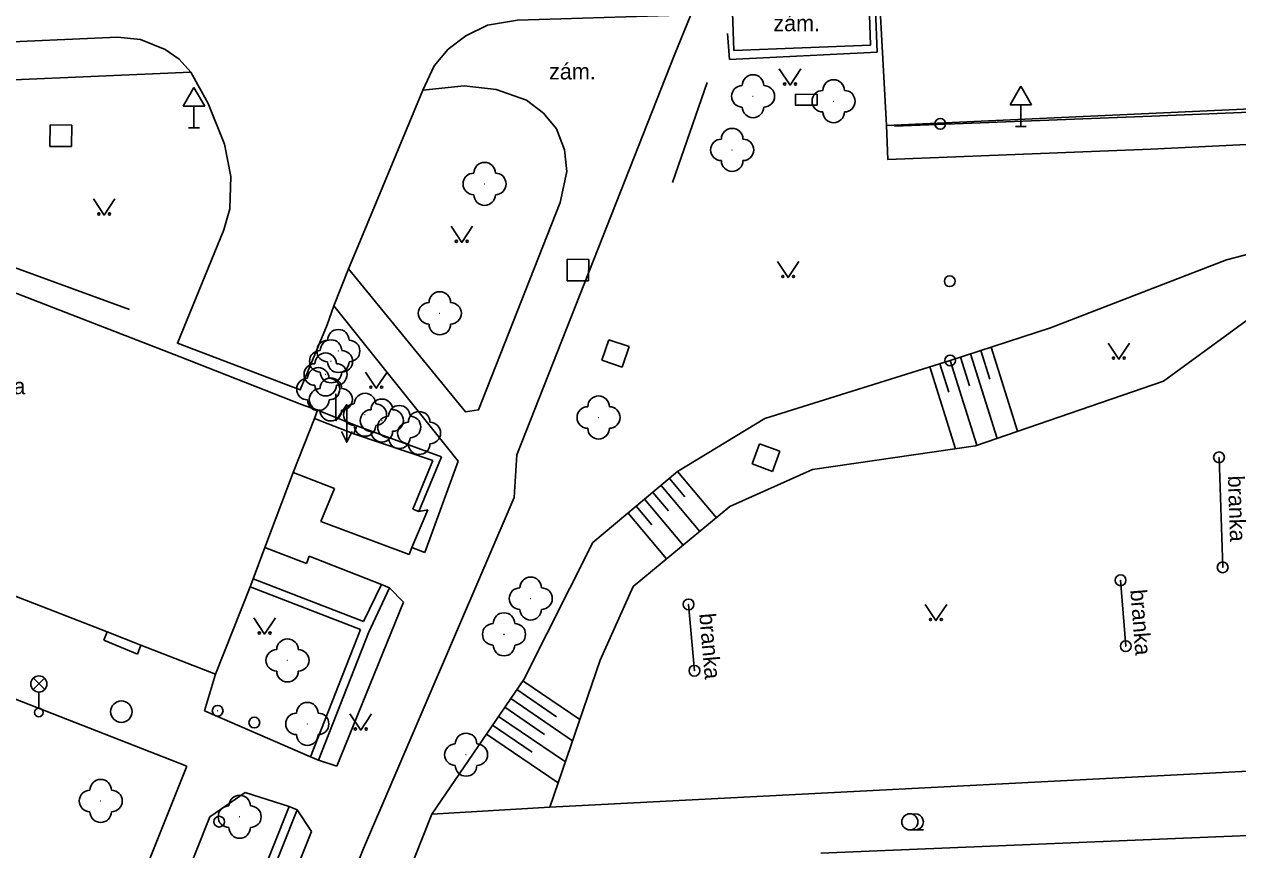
# Model space of a CAD drawing. Extents: x -737812 to -729375, y -1123000 to -1115500.
# Drawn here: x -736631 to -736574.7, y -1118354.6 to -1118316.3 of the extents above; entities that cross this region are included whole.
import ezdxf

# ---------------------------------------------------------------- set-up
doc = ezdxf.new("R2010")
doc.units = 0
for name, color, linetype in [('Doplněk polohopisu', 7, 'Continuous'), ('Doplňkové značky', 7, 'Continuous'), ('Hranice - ploty_ zdi', 7, 'Continuous'), ('Komunikace', 7, 'Continuous'), ('Pomocné popisy', 7, 'Continuous'), ('Popisy budov', 7, 'Continuous'), ('Povr_ zn_ inž_ sítí - el_', 7, 'Continuous'), ('Povr_ zn_ inž_ sítí - kan_', 7, 'Continuous'), ('Povr_ zn_ inž_ sítí - ner_', 7, 'Continuous'), ('Povr_ zn_ inž_ sítí - pl_', 7, 'Continuous'), ('Povr_ zn_ inž_ sítí - tep_', 7, 'Continuous'), ('Stavební objekty', 7, 'Continuous'), ('Výškopis', 7, 'Continuous'), ('Zeleň', 7, 'Continuous'), ('Značky druhů pozemků', 7, 'Continuous')]:
    doc.layers.add(name, color=color, linetype=linetype)

msp = doc.modelspace()

# ---------------------------------------------------------------- linework, layer by layer
at = {"layer": 'Doplněk polohopisu'}
for p, q in [((-736598.1, -1118317.51), (-736598.16, -1118315.74)), ((-736591.82, -1118315.38), (-736591.76, -1118317.25)), ((-736591.76, -1118317.25), (-736598.1, -1118317.51)), ((-736616.67, -1118329.36), (-736610.9, -1118336.57))]:
    msp.add_line(p, q, dxfattribs=at)
for points in [[(-736600.09, -1118315.84), (-736600.85, -1118317.7), (-736608.17, -1118336.28), (-736608.3, -1118338.26)], [(-736641.9, -1118319.3), (-736641.47, -1118319.3), (-736640.46, -1118319.26), (-736623.31, -1118318.51)], [(-736615.99, -1118327.65), (-736610.56, -1118334.29), (-736609.95, -1118334.2), (-736606.16, -1118324.57), (-736605.85, -1118323.13), (-736605.96, -1118322.12), (-736606.33, -1118321.14), (-736606.94, -1118320.42), (-736607.73, -1118319.81), (-736609.14, -1118319.31), (-736610.62, -1118319.14), (-736612.54, -1118319.34)], [(-736612.45, -1118340.82), (-736610.9, -1118336.57)], [(-736615.29, -1118354.56), (-736608.3, -1118338.26)], [(-736613.05, -1118340.59), (-736612.45, -1118340.82)], [(-736614.09, -1118342.46), (-736613.44, -1118343.13)], [(-736616.53, -1118350.75), (-736613.44, -1118343.13)], [(-736622.16, -1118346.47), (-736622.67, -1118348.17)], [(-736632.88, -1118347.08), (-736623.5, -1118350.75)], [(-736622.67, -1118348.17), (-736617.75, -1118350.31)], [(-736623.5, -1118350.75), (-736634.73, -1118378.78)], [(-736616.53, -1118350.75), (-736617.38, -1118350.46)], [(-736622.43, -1118353.1), (-736620.78, -1118351.97)], [(-736620.78, -1118351.97), (-736618.74, -1118352.62)], [(-736617.7, -1118353.77), (-736618.37, -1118352.77)], [(-736633.17, -1118380.05), (-736622.43, -1118353.1)], [(-736632.97, -1118392.02), (-736617.7, -1118353.77)], [(-736615.29, -1118354.56), (-736630.74, -1118393.32)]]:
    msp.add_lwpolyline(points, dxfattribs=at)
at = {"layer": 'Doplňkové značky'}
for p, q in [((-736623.16, -1118319.224), (-736623.66, -1118320.09)), ((-736623.16, -1118319.224), (-736622.66, -1118320.09)), ((-736584.78, -1118319.164), (-736585.28, -1118320.03)), ((-736584.78, -1118319.164), (-736584.28, -1118320.03)), ((-736623.66, -1118320.09), (-736622.66, -1118320.09)), ((-736623.16, -1118321.09), (-736623.16, -1118320.09)), ((-736585.28, -1118320.03), (-736584.28, -1118320.03)), ((-736584.78, -1118321.03), (-736584.78, -1118320.03)), ((-736623.41, -1118321.09), (-736622.91, -1118321.09)), ((-736585.03, -1118321.03), (-736584.53, -1118321.03))]:
    msp.add_line(p, q, dxfattribs=at)
for centre, radius in [((-736575.581, -1118336.4), 0.25), ((-736575.581, -1118336.4), 0.0005), ((-736575.41, -1118341.51), 0.25), ((-736575.41, -1118341.51), 0.0005), ((-736580.15, -1118342.11), 0.25), ((-736580.15, -1118342.11), 0.0005), ((-736600.201, -1118343.23), 0.25), ((-736600.201, -1118343.23), 0.0005), ((-736579.91, -1118345.17), 0.25), ((-736579.91, -1118345.17), 0.0005), ((-736599.931, -1118346.31), 0.25), ((-736599.931, -1118346.31), 0.0005), ((-736622.061, -1118348.17), 0.25), ((-736622.061, -1118348.17), 0.0005)]:
    msp.add_circle(centre, radius, dxfattribs=at)
at = {"layer": 'Hranice - ploty_ zdi'}
for p, q in [((-736575.58, -1118336.4), (-736575.41, -1118341.51)), ((-736580.15, -1118342.11), (-736579.91, -1118345.17)), ((-736600.2, -1118343.23), (-736599.93, -1118346.31))]:
    msp.add_line(p, q, dxfattribs=at)
for points in [[(-736598.39, -1118316.71), (-736598.3, -1118317.92), (-736591.45, -1118317.58), (-736591.52, -1118315.63)], [(-736599.34, -1118318.99), (-736600.95, -1118323.63)], [(-736535.57, -1118318.81), (-736549.9, -1118319.31), (-736564.27, -1118319.97), (-736578.72, -1118320.56), (-736590.64, -1118321.02)], [(-736626.16, -1118329.53), (-736640.74, -1118324.21)], [(-736615.6, -1118334.93), (-736611.67, -1118336.38)], [(-736612.07, -1118336.55), (-736615.74, -1118335.31)], [(-736613, -1118338.8), (-736612.07, -1118336.55)], [(-736612.72, -1118338.91), (-736611.67, -1118336.38)], [(-736618.55, -1118337.11), (-736616.64, -1118337.85)], [(-736616.64, -1118337.85), (-736617.27, -1118339.38)], [(-736613.05, -1118340.59), (-736612.31, -1118338.83)], [(-736613, -1118338.8), (-736612.72, -1118338.91)], [(-736612.72, -1118338.91), (-736612.31, -1118338.83)], [(-736617.27, -1118339.38), (-736613.17, -1118340.91)], [(-736617.93, -1118341.33), (-736619.87, -1118340.58)], [(-736613.05, -1118340.59), (-736613.17, -1118340.91)], [(-736617.93, -1118341.33), (-736617.81, -1118340.99)], [(-736614.09, -1118342.46), (-736614.46, -1118342.31), (-736617.81, -1118340.99)], [(-736615.29, -1118344.03), (-736620.42, -1118342.04)], [(-736615.29, -1118344.03), (-736614.46, -1118342.31)], [(-736615.43, -1118344.4), (-736620.56, -1118342.41)], [(-736615.06, -1118344.55), (-736614.09, -1118342.46)], [(-736615.43, -1118344.4), (-736617.75, -1118350.31)], [(-736617.38, -1118350.46), (-736615.06, -1118344.55)], [(-736544.96, -1118349.41), (-736574.22, -1118350.98), (-736606.64, -1118352.65), (-736612.12, -1118352.97)], [(-736617.75, -1118350.31), (-736617.38, -1118350.46)], [(-736642.52, -1118412.31), (-736618.74, -1118352.62)], [(-736618.37, -1118352.77), (-736642.17, -1118412.52)], [(-736612.12, -1118352.97), (-736618.92, -1118370.09), (-736634.09, -1118408.3)], [(-736618.74, -1118352.62), (-736618.37, -1118352.77)]]:
    msp.add_lwpolyline(points, dxfattribs=at)
at = {"layer": 'Komunikace'}
msp.add_line((-736615.99, -1118327.65), (-736616.67, -1118329.36), dxfattribs=at)
for points in [[(-736612.54, -1118319.34), (-736612.01, -1118318.22), (-736611.36, -1118317.44), (-736610.54, -1118316.83), (-736609.54, -1118316.33), (-736608.14, -1118316.09), (-736600.09, -1118315.84)], [(-736591.82, -1118315.38), (-736591.32, -1118315.35), (-736591.02, -1118320.98), (-736535.87, -1118318.46)], [(-736731.01, -1118328.82), (-736730.6, -1118327.33), (-736729.76, -1118325.55), (-736728.47, -1118323.96), (-736727.37, -1118322.97), (-736726.14, -1118322.1), (-736724.73, -1118321.56), (-736723.69, -1118321.36), (-736722.72, -1118321.32), (-736721.74, -1118321.25), (-736718.75, -1118321.11), (-736717.71, -1118321.12), (-736666.72, -1118318.51), (-736643.67, -1118317.64), (-736642.68, -1118317.57), (-736641.67, -1118317.52), (-736640.7, -1118317.51), (-736626.71, -1118316.89), (-736625.65, -1118316.99), (-736624.5, -1118317.46), (-736623.85, -1118317.9), (-736623.31, -1118318.51)], [(-736623.31, -1118318.51), (-736622.5, -1118319.97), (-736621.75, -1118321.86), (-736621.45, -1118323.35), (-736621.5, -1118324.86), (-736621.78, -1118325.83), (-736623.93, -1118331.1), (-736618.23, -1118333.27), (-736616.98, -1118330.25), (-736616.67, -1118329.36)], [(-736615.99, -1118327.65), (-736615.54, -1118326.57), (-736612.54, -1118319.34)]]:
    msp.add_lwpolyline(points, dxfattribs=at)
at = {"layer": 'Povr_ zn_ inž_ sítí - el_'}
for p, q in [((-736630.624, -1118347.188), (-736630.096, -1118346.66)), ((-736630.088, -1118347.185), (-736630.616, -1118346.656)), ((-736630.36, -1118347.3), (-736630.36, -1118348.05))]:
    msp.add_line(p, q, dxfattribs=at)
msp.add_lwpolyline([(-736594.24, -1118319.539), (-736595.24, -1118319.541), (-736595.24, -1118320.041), (-736594.24, -1118320.039)], close=True, dxfattribs=at)
for points in [[(-736616.57, -1118333.45), (-736616.57, -1118334.7), (-736616.07, -1118333.95), (-736616.07, -1118335.7)], [(-736616.32, -1118335.2), (-736616.07, -1118335.7), (-736615.82, -1118335.2)]]:
    msp.add_lwpolyline(points, dxfattribs=at)
for centre, radius in [((-736630.36, -1118346.925), 0.375), ((-736630.36, -1118348.25), 0.2), ((-736620.36, -1118348.72), 0.25), ((-736621.99, -1118353.32), 0.25)]:
    msp.add_circle(centre, radius, dxfattribs=at)
at = {"layer": 'Povr_ zn_ inž_ sítí - kan_'}
msp.add_circle((-736626.53, -1118348.21), 0.5, dxfattribs=at)
at = {"layer": 'Povr_ zn_ inž_ sítí - ner_'}
for p, q in [((-736596.906, -1118335.768), (-736597.252, -1118336.706)), ((-736595.968, -1118336.114), (-736596.906, -1118335.768)), ((-736596.314, -1118337.052), (-736595.968, -1118336.114)), ((-736597.252, -1118336.706), (-736596.314, -1118337.052))]:
    msp.add_line(p, q, dxfattribs=at)
at = {"layer": 'Povr_ zn_ inž_ sítí - pl_'}
for centre in [(-736588.52, -1118320.91), (-736588.08, -1118328.22), (-736588.06, -1118331.9)]:
    msp.add_circle(centre, 0.25, dxfattribs=at)
at = {"layer": 'Povr_ zn_ inž_ sítí - tep_'}
for p, q in [((-736629.835, -1118320.955), (-736629.845, -1118321.955)), ((-736628.835, -1118320.965), (-736629.835, -1118320.955)), ((-736628.845, -1118321.965), (-736628.835, -1118320.965)), ((-736629.845, -1118321.955), (-736628.845, -1118321.965)), ((-736605.835, -1118327.195), (-736605.845, -1118328.195)), ((-736604.835, -1118327.205), (-736605.835, -1118327.195)), ((-736604.845, -1118328.205), (-736604.835, -1118327.205)), ((-736605.845, -1118328.195), (-736604.845, -1118328.205)), ((-736603.911, -1118330.935), (-736604.235, -1118331.881)), ((-736602.965, -1118331.259), (-736603.911, -1118330.935)), ((-736603.289, -1118332.205), (-736602.965, -1118331.259)), ((-736604.235, -1118331.881), (-736603.289, -1118332.205))]:
    msp.add_line(p, q, dxfattribs=at)
at = {"layer": 'Stavební objekty'}
for points in [[(-736617.43, -1118334.21), (-736618.17, -1118333.94), (-736623.8, -1118331.73), (-736640.97, -1118325.07), (-736641.4, -1118324.9)], [(-736617.43, -1118334.21), (-736617.57, -1118334.59)], [(-736615.6, -1118334.93), (-736617.43, -1118334.21)], [(-736618.55, -1118337.11), (-736617.57, -1118334.59)], [(-736617.57, -1118334.59), (-736615.74, -1118335.31)], [(-736615.74, -1118335.31), (-736615.6, -1118334.93)], [(-736619.87, -1118340.58), (-736618.55, -1118337.11)], [(-736620.56, -1118342.41), (-736620.42, -1118342.04), (-736619.87, -1118340.58)], [(-736632.87, -1118342.3), (-736631.22, -1118342.94), (-736627.19, -1118344.51), (-736625.63, -1118345.12), (-736622.16, -1118346.47)], [(-736622.16, -1118346.47), (-736620.56, -1118342.41)], [(-736627.34, -1118344.89), (-736627.19, -1118344.51)], [(-736627.34, -1118344.89), (-736625.79, -1118345.54)], [(-736625.79, -1118345.54), (-736625.63, -1118345.12)]]:
    msp.add_lwpolyline(points, dxfattribs=at)
at = {"layer": 'Výškopis'}
for p, q in [((-736585.88, -1118335.52), (-736587.11, -1118331.59)), ((-736586.22, -1118332.77), (-736586.63, -1118331.44)), ((-736584.93, -1118335.19), (-736586.16, -1118331.28)), ((-736588.12, -1118333.38), (-736588.54, -1118332.05)), ((-736586.82, -1118335.84), (-736588.06, -1118331.9)), ((-736587.17, -1118333.08), (-736587.58, -1118331.75)), ((-736587.82, -1118336), (-736589.01, -1118332.2)), ((-736598.91, -1118339.21), (-736600.71, -1118337.06)), ((-736599.68, -1118339.85), (-736601.48, -1118337.7)), ((-736600.37, -1118338.24), (-736601.09, -1118337.38)), ((-736600.45, -1118340.48), (-736602.24, -1118338.35)), ((-736601.14, -1118338.88), (-736601.86, -1118338.03)), ((-736601.91, -1118339.53), (-736602.63, -1118338.67)), ((-736601.22, -1118341.12), (-736603.01, -1118338.99))]:
    msp.add_line(p, q, dxfattribs=at)
for points in [[(-736607.85, -1118346.72), (-736604.64, -1118340.36), (-736600.71, -1118337.06), (-736596.67, -1118334.6), (-736588.06, -1118331.9), (-736583.4, -1118330.39), (-736575.24, -1118327.22), (-736563.92, -1118324.29), (-736552.28, -1118322.49), (-736546.76, -1118323.72), (-736552.86, -1118324.88), (-736559.84, -1118325.66), (-736572.03, -1118328.38), (-736578.15, -1118332.86), (-736586.88, -1118335.86), (-736594.45, -1118336.97), (-736598.28, -1118338.69), (-736602.77, -1118342.4), (-736604.31, -1118345.82)], [(-736606.64, -1118352.65), (-736604.31, -1118345.82)], [(-736607.85, -1118346.72), (-736612.12, -1118352.97)], [(-736607.89, -1118346.78), (-736605.25, -1118348.58)], [(-736608.17, -1118347.19), (-736606.33, -1118348.45)], [(-736608.45, -1118347.6), (-736605.59, -1118349.56)], [(-736609.02, -1118348.43), (-736605.92, -1118350.54)], [(-736608.73, -1118348.01), (-736606.89, -1118349.27)], [(-736609.3, -1118348.84), (-736607.46, -1118350.1)], [(-736609.58, -1118349.25), (-736606.26, -1118351.52)]]:
    msp.add_lwpolyline(points, dxfattribs=at)
at = {"layer": 'Zeleň'}
for points in [[(-736535.54, -1118320.09), (-736549.85, -1118320.78), (-736564.14, -1118321.37), (-736578.74, -1118322.08), (-736590.95, -1118322.57), (-736591.02, -1118320.98)], [(-736571.98, -1118353.87), (-736594.07, -1118354.79)]]:
    msp.add_lwpolyline(points, dxfattribs=at)
for centre in [(-736597.21, -1118319.63), (-736593.47, -1118319.86), (-736598.18, -1118322.12), (-736609.67, -1118323.7), (-736611.75, -1118329.71), (-736616.46, -1118331.46), (-736616.8, -1118331.94), (-736617.05, -1118332.55), (-736617.39, -1118333.23), (-736616.81, -1118333.71), (-736615.22, -1118334.42), (-736614.44, -1118334.69), (-736613.63, -1118334.99), (-736604.38, -1118334.55), (-736612.71, -1118335.27), (-736607.53, -1118342.96), (-736608.77, -1118344.62), (-736618.82, -1118345.83), (-736617.9, -1118348.78), (-736610.53, -1118350.21), (-736627.49, -1118352.36), (-736621.04, -1118353.09)]:
    msp.add_circle(centre, 0.0005, dxfattribs=at)
for centre, start, end in [((-736597.21, -1118319.13), 360, 180), ((-736597.71, -1118319.63), 90, 270), ((-736596.71, -1118319.63), 270, 90), ((-736593.47, -1118319.36), 360, 180), ((-736593.97, -1118319.86), 90, 270), ((-736592.97, -1118319.86), 270, 90), ((-736597.21, -1118320.13), 180, 360), ((-736593.47, -1118320.36), 180, 360), ((-736598.18, -1118321.62), 360, 180), ((-736598.68, -1118322.12), 90, 270), ((-736597.68, -1118322.12), 270, 90), ((-736598.18, -1118322.62), 180, 360), ((-736609.67, -1118323.2), 360, 180), ((-736610.17, -1118323.7), 90, 270), ((-736609.17, -1118323.7), 270, 90), ((-736609.67, -1118324.2), 180, 360), ((-736611.75, -1118329.21), 360, 180), ((-736612.25, -1118329.71), 90, 270), ((-736611.25, -1118329.71), 270, 90), ((-736616.46, -1118330.96), 360, 180), ((-736611.75, -1118330.21), 180, 360), ((-736616.96, -1118331.46), 90, 270), ((-736616.8, -1118331.44), 360, 180), ((-736615.96, -1118331.46), 270, 90), ((-736617.3, -1118331.94), 90, 270), ((-736617.05, -1118332.05), 360, 180), ((-736616.3, -1118331.94), 270, 90), ((-736617.55, -1118332.55), 90, 270), ((-736616.46, -1118331.96), 180, 360), ((-736616.55, -1118332.55), 270, 90), ((-736617.89, -1118333.23), 90, 270), ((-736617.39, -1118332.73), 360, 180), ((-736616.81, -1118333.21), 360, 180), ((-736616.8, -1118332.44), 180, 360), ((-736616.89, -1118333.23), 270, 90), ((-736617.31, -1118333.71), 90, 270), ((-736617.05, -1118333.05), 180, 360), ((-736616.31, -1118333.71), 270, 90), ((-736617.39, -1118333.73), 180, 360), ((-736615.22, -1118333.92), 360, 180), ((-736614.44, -1118334.19), 360, 180), ((-736604.38, -1118334.05), 360, 180), ((-736616.81, -1118334.21), 180, 360), ((-736615.72, -1118334.42), 90, 270), ((-736614.94, -1118334.69), 90, 270), ((-736614.72, -1118334.42), 270, 90), ((-736613.63, -1118334.49), 360, 180), ((-736613.94, -1118334.69), 270, 90), ((-736612.71, -1118334.77), 360, 180), ((-736604.88, -1118334.55), 90, 270), ((-736603.88, -1118334.55), 270, 90), ((-736615.22, -1118334.92), 180, 360), ((-736614.13, -1118334.99), 90, 270), ((-736613.21, -1118335.27), 90, 270), ((-736613.13, -1118334.99), 270, 90), ((-736612.21, -1118335.27), 270, 90), ((-736614.44, -1118335.19), 180, 360), ((-736613.63, -1118335.49), 180, 360), ((-736604.38, -1118335.05), 180, 360), ((-736612.71, -1118335.77), 180, 360), ((-736607.53, -1118342.46), 360, 180), ((-736608.03, -1118342.96), 90, 270), ((-736607.03, -1118342.96), 270, 90), ((-736607.53, -1118343.46), 180, 360), ((-736608.77, -1118344.12), 360, 180), ((-736609.27, -1118344.62), 90, 270), ((-736608.27, -1118344.62), 270, 90), ((-736618.82, -1118345.33), 360, 180), ((-736608.77, -1118345.12), 180, 360), ((-736619.32, -1118345.83), 90, 270), ((-736618.32, -1118345.83), 270, 90), ((-736618.82, -1118346.33), 180, 360), ((-736617.9, -1118348.28), 360, 180), ((-736618.4, -1118348.78), 90, 270), ((-736617.4, -1118348.78), 270, 90), ((-736617.9, -1118349.28), 180, 360), ((-736610.53, -1118349.71), 360, 180), ((-736611.03, -1118350.21), 90, 270), ((-736610.03, -1118350.21), 270, 90), ((-736610.53, -1118350.71), 180, 360), ((-736627.99, -1118352.36), 90, 270), ((-736627.49, -1118351.86), 360, 180), ((-736626.99, -1118352.36), 270, 90), ((-736621.04, -1118352.59), 360, 180), ((-736627.49, -1118352.86), 180, 360), ((-736621.54, -1118353.09), 90, 270), ((-736620.54, -1118353.09), 270, 90), ((-736621.04, -1118353.59), 180, 360)]:
    msp.add_arc(centre, 0.5, start, end, dxfattribs=at)
at = {"layer": 'Značky druhů pozemků'}
msp.add_line((-736589.93, -1118353.705), (-736589.305, -1118353.705), dxfattribs=at)
for points in [[(-736595.99, -1118318.36), (-736595.49, -1118319.11), (-736594.99, -1118318.36)], [(-736627.83, -1118324.4), (-736627.33, -1118325.15), (-736626.83, -1118324.4)], [(-736611.23, -1118325.67), (-736610.73, -1118326.42), (-736610.23, -1118325.67)], [(-736596.08, -1118327.3), (-736595.58, -1118328.05), (-736595.08, -1118327.3)], [(-736580.73, -1118331.09), (-736580.23, -1118331.84), (-736579.73, -1118331.09)], [(-736615.2, -1118332.44), (-736614.7, -1118333.19), (-736614.2, -1118332.44)], [(-736589.22, -1118343.23), (-736588.72, -1118343.98), (-736588.22, -1118343.23)], [(-736620.38, -1118343.86), (-736619.88, -1118344.61), (-736619.38, -1118343.86)], [(-736615.92, -1118348.32), (-736615.42, -1118349.07), (-736614.92, -1118348.32)]]:
    msp.add_lwpolyline(points, dxfattribs=at)
for centre, radius in [((-736595.74, -1118319.06), 0.05), ((-736595.24, -1118319.06), 0.05), ((-736627.58, -1118325.1), 0.05), ((-736627.08, -1118325.1), 0.05), ((-736610.98, -1118326.37), 0.05), ((-736610.48, -1118326.37), 0.05), ((-736595.83, -1118328), 0.05), ((-736595.33, -1118328), 0.05), ((-736580.48, -1118331.79), 0.05), ((-736579.98, -1118331.79), 0.05), ((-736614.95, -1118333.14), 0.05), ((-736614.45, -1118333.14), 0.05), ((-736588.97, -1118343.93), 0.05), ((-736588.47, -1118343.93), 0.05), ((-736620.13, -1118344.56), 0.05), ((-736619.63, -1118344.56), 0.05), ((-736615.67, -1118349.02), 0.05), ((-736615.17, -1118349.02), 0.05), ((-736589.93, -1118353.33), 0.375)]:
    msp.add_circle(centre, radius, dxfattribs=at)
msp.add_arc((-736589.68, -1118353.33), 0.375, 249.4944, 109.0474, dxfattribs=at)

# ---------------------------------------------------------------- texts
at = {"layer": 'Pomocné popisy'}
for p in [(-736596.27, -1118316.61), (-736606.68, -1118318.85)]:
    msp.add_text('zám.', height=0.75, dxfattribs=at).set_placement(p)
for rotation, p in [(271.9054, (-736575.17, -1118337.26)), (274.4846, (-736579.7, -1118342.56)), (275.0099, (-736599.71, -1118343.67))]:
    msp.add_text('branka', height=0.75, rotation=rotation, dxfattribs=at).set_placement(p)
at = {"layer": 'Popisy budov'}
msp.add_text('školní jídelna', height=0.75, dxfattribs=at).set_placement((-736636.84, -1118333.47))

doc.saveas('drawing.dxf')
